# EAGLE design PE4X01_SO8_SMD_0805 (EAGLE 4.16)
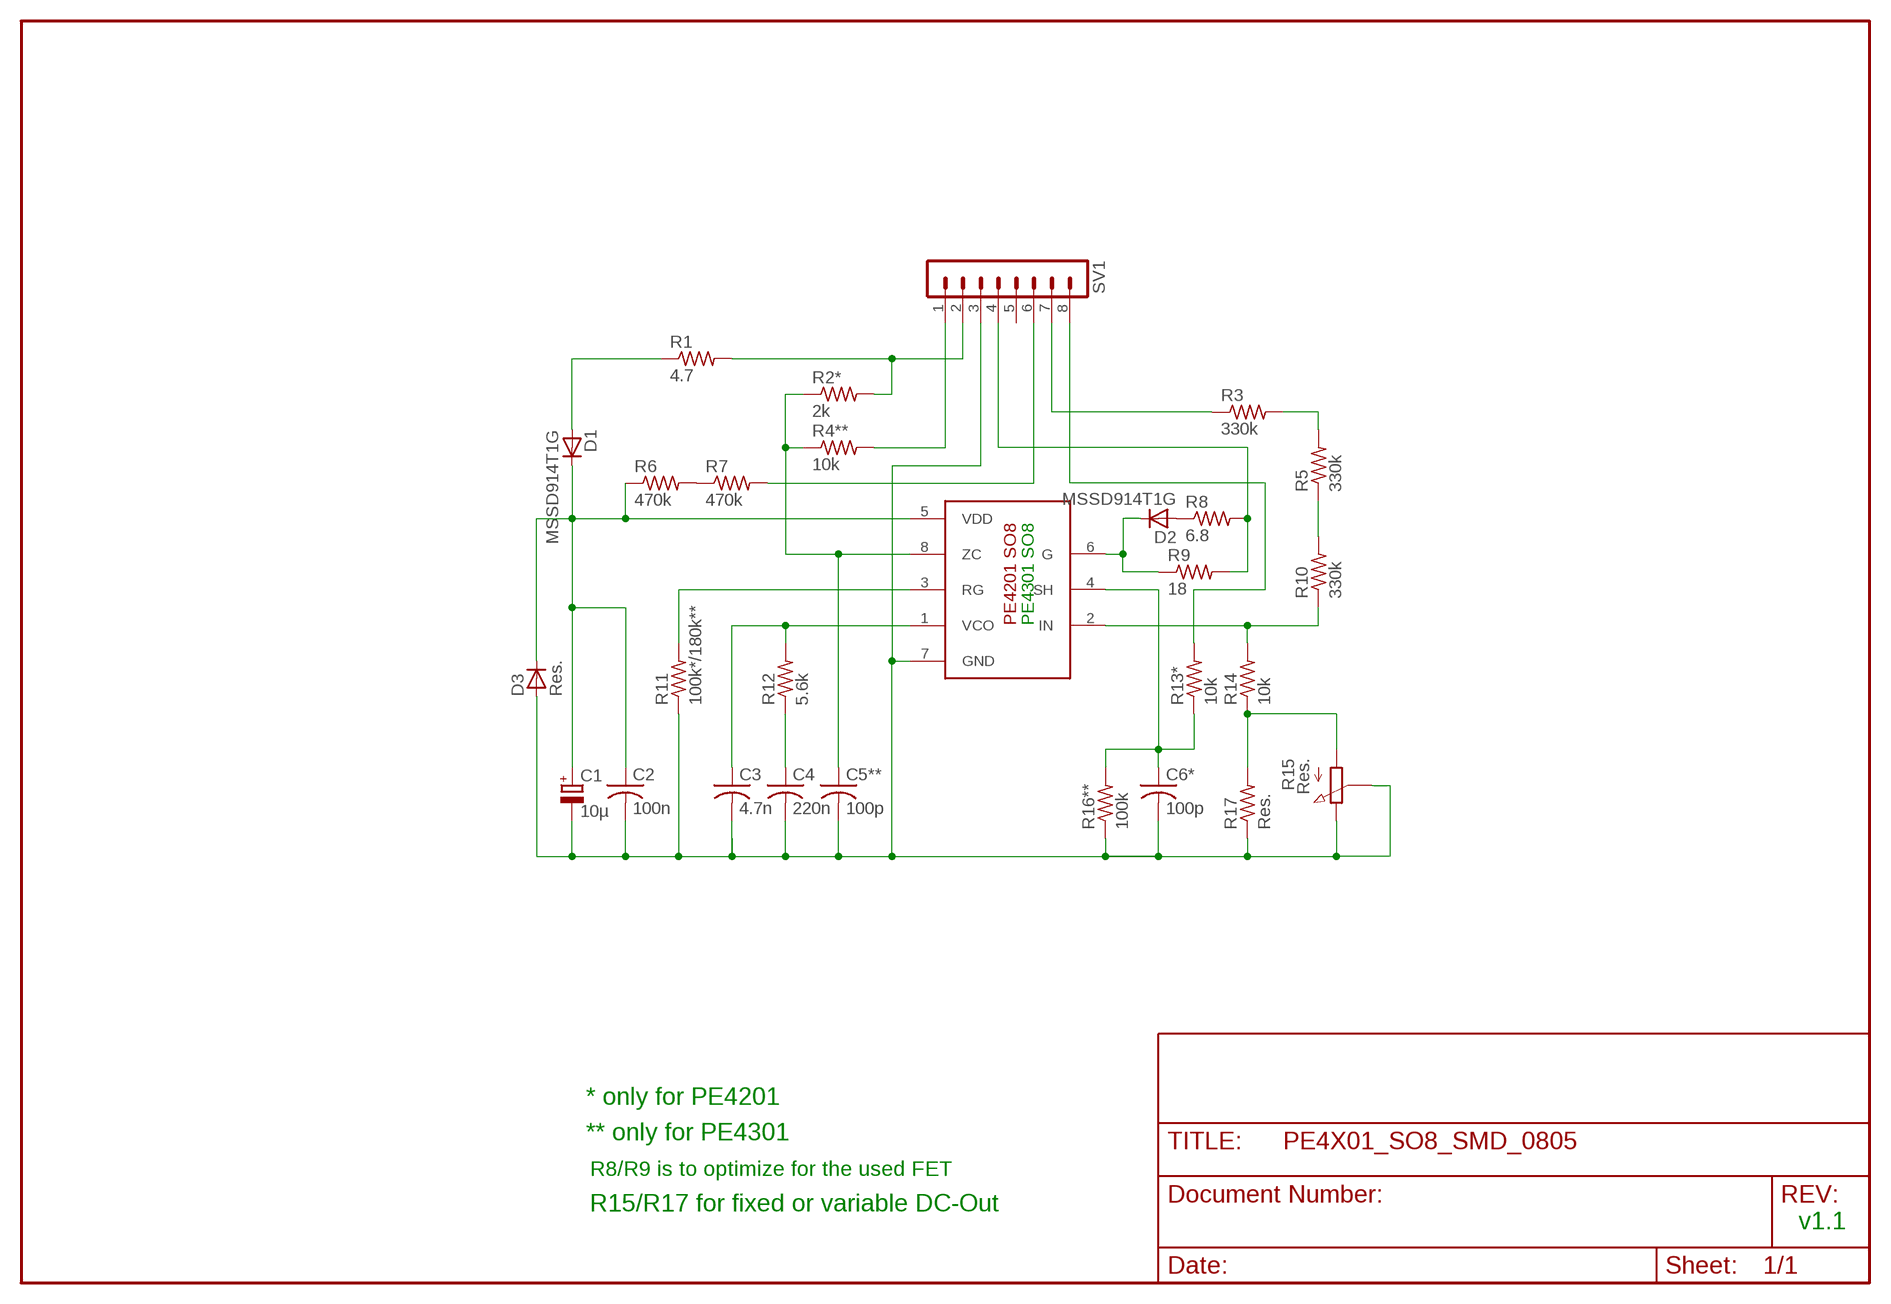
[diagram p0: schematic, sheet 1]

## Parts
C1  10µ  CPOL-EU153CLV-0405  [153CLV-0405]
C2  100n  C-USC1206K  [C1206K]
C3  4.7n  C-USC0805  [C0805]
C4  220n  C-USC0805  [C0805]
C5**  100p  C-USC0805  [C0805]
C6*  100p  C-USC0805  [C0805]
D1  MSSD914T1G  D-SOD123  [SOD123]
D2  MSSD914T1G  D-SOD123  [SOD123]
D3  Res.  D-SOD123  [SOD123]
R1  4.7  R-US_R0805  [R0805]
R2*  2k  R-US_R0805  [R0805]
R3  330k  R-US_R0805  [R0805]
R4**  10k  R-US_R0805  [R0805]
R5  330k  R-US_R0805  [R0805]
R6  470k  R-US_R0805  [R0805]
R7  470k  R-US_R0805  [R0805]
R8  6.8  R-US_R0805  [R0805]
R9  18  R-US_R0805  [R0805]
R10  330k  R-US_R0805  [R0805]
R11  100k*/180k**  R-US_R0805  [R0805]
R12  5.6k  R-US_R0805  [R0805]
R13*  10k  R-US_R0805  [R0805]
R14  10k  R-US_R0805  [R0805]
R15  Res.  PC25  [PC25]
R16**  100k  R-US_R0805  [R0805]
R17  Res.  R-US_R0805  [R0805]
SV1  MA08-1  [MA08-1]
U$1  PE4201/4301_SO08  PE4201_SO08  [PE4201_SO08]

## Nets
++: C6*.1 R13*.1 R16**.2 U$1.4(SH)
A1: C1.+ C2.1 D1.1(C) D3.1(C) R6.1 U$1.5(VDD)
A3: R11.2 U$1.3(RG)
A4: C3.1 R12.2 U$1.1(VCO)
CS: C5**.1 R2*.1 R4**.1 U$1.8(ZC)
GND: C1.- C2.2 C3.2 C4.2 C5**.2 C6*.2 D3.2(A) R11.1 R15.E R15.S R16**.1 R17.1 SV1.3 U$1.7(GND)
N$6: D2.1(C) R9.1 U$1.6(G)
N$9: D2.2(A) R8.1
N$12: R6.2 R7.1
N$13: R1.2 R2*.2 SV1.2
N$14: R10.1 R14.2 U$1.2(IN)
N$16: R5.1 R10.2
N$19: R7.2 SV1.6
N$21: R4**.2 SV1.1
N$22: C4.1 R12.1
N$23: R3.2 R5.2
N$24: R3.1 SV1.7
N$25: R8.2 R9.2 SV1.4
N$26: R13*.2 SV1.8
N$27: D1.2(A) R1.1
N$28: R14.1 R15.A R17.2
Unconnected: SV1.5

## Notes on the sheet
- PE4301 SO8
- * only for PE4201
- ** only for PE4301
- R8/R9 is to optimize for the used FET
- R15/R17 for fixed or variable DC-Out
- v1.1

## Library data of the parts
C1 = rcl:CPOL-EU: POLARIZED CAPACITOR, European symbol
C2-C4 C5** C6* = rcl:C-US: CAPACITOR, American symbol
D1-D3 = semicon-smd-ipc:D-: DIODE
R1 R2* R3 R4** R5-R12 R13* R14 R16** R17 = rcl:R-US_: RESISTOR, American symbol
R15 = pot-vitrohm:PC25: VITROHM POTENTIOMETER
SV1 = con-lstb:MA08-1: PIN HEADER
U$1 = PE4201:PE4201_SO08

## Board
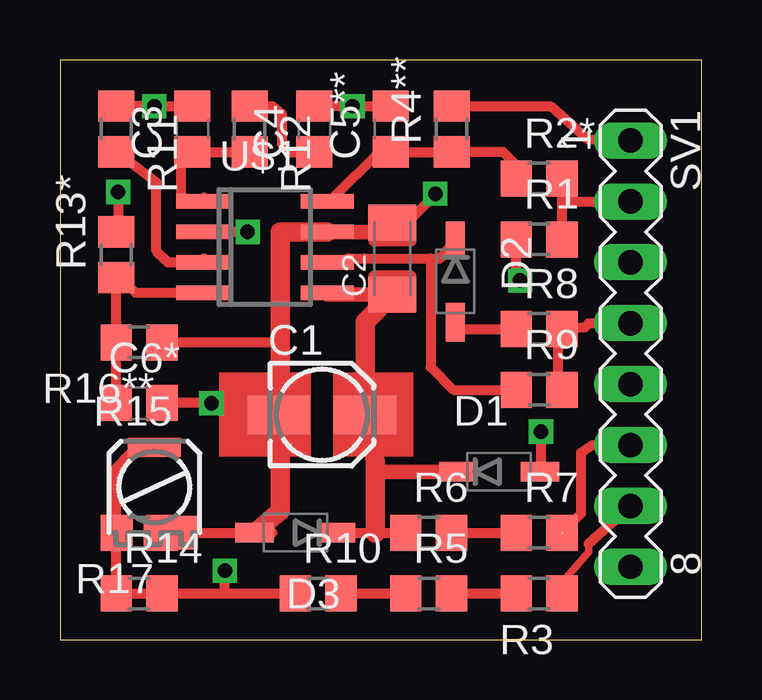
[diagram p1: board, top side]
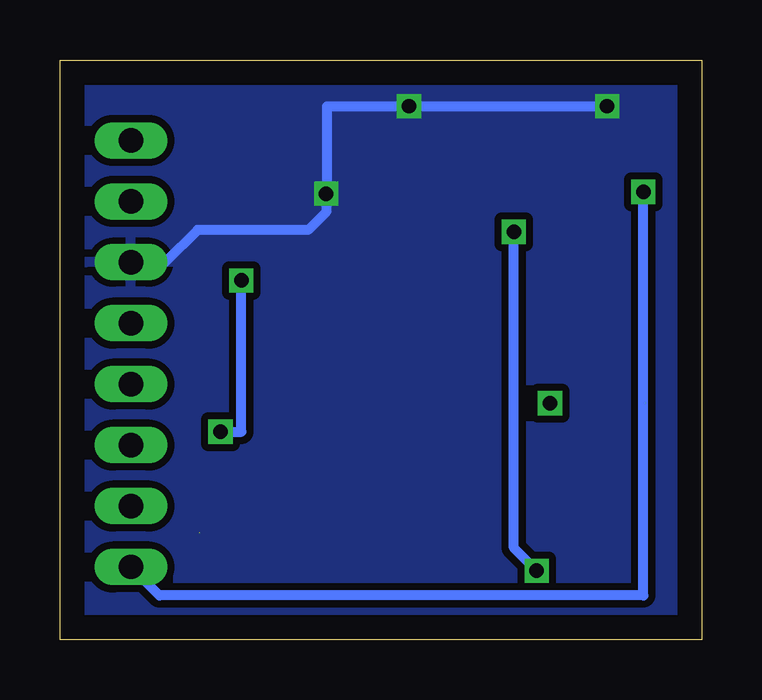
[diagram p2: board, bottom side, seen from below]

Size 26.73 x 24.18 mm. Coordinates in mm from the lower left corner, seen from the top.
Outline: 0,0 26.73,0 26.73,24.18 0,24.18 0,0
Copper layers (1*16): Top 0.035mm / dielectric 1.5mm / Bottom 0.035mm
Design rules "default": minimum track width 10mil, minimum drill 24mil, track to track 8mil, track to pad 8mil, pad to pad 8mil, via to via 8mil, smd to smd 8mil, copper to edge 40mil, drill to drill 8mil, minimum pad ring 10mil, minimum via ring 8mil, stop-mask expansion 4mil, vias tented up to drill 0mil, thermal gap 10mil

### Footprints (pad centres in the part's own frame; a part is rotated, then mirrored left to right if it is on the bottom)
153CLV-0405 = smd 2.6 x 1.6: + 1.8,0; - -1.8,0
C1206K = smd 1.5 x 2: 1 -1.5,0; 2 1.5,0
C0805 = smd 1.3 x 1.5: 1 -0.95,0; 2 0.95,0
SOD123 = smd 1.6 x 0.8: 1 -1.7,0; 2 1.7,0
R0805 = smd 1.3 x 1.5: 1 -0.95,0; 2 0.95,0
PC25 = smd 2.2 x 0.8: 4 0,1.65 | smd 0.9 x 1.4: A -1.35,-1.9; E 1.35,-1.9; S 0,-1.9
MA08-1 = drill 1.016 long: 1 -8.89,0; 2 -6.35,0; 3 -3.81,0; 4 -1.27,0; 5 1.27,0; 6 3.81,0; 7 6.35,0; 8 8.89,0
PE4201_SO08 = smd 0.6 x 2.2: 1 -1.905,-2.6; 2 -0.635,-2.6; 3 0.635,-2.6; 4 1.905,-2.6; 5 1.905,2.6; 6 0.635,2.6; 7 -0.635,2.6; 8 -1.905,2.6

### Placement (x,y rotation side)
C1  10.92,9.39 0 top
C2  13.85,15.9 90 top
C3  5.52,21.29 90 top
C4  10.6,21.29 90 top
C5**  13.77,21.29 90 top
C6*  3.3,9.86 0 top
D1  18.3,7.01 0 top
D2  16.47,14.94 270 top
D3  9.8,4.47 180 top
R1  19.96,16.69 0 top
R2*  19.97,19.23 0 top
R3  19.96,1.93 180 top
R4**  16.31,21.29 90 top
R5  15.36,1.93 0 top
R6  15.36,4.47 0 top
R7  19.96,4.47 0 top
R8  19.96,12.96 0 top
R9  19.97,10.42 0 top
R10  10.76,1.93 0 top
R11  2.34,21.29 270 top
R12  7.9,21.29 270 top
R13*  2.34,16.06 90 top
R14  3.3,1.93 0 top
R15  3.93,6.37 0 top
R16**  3.3,12.4 180 top
R17  3.3,4.47 180 top
SV1  23.77,11.93 270 top
U$1  8.54,16.37 270 top

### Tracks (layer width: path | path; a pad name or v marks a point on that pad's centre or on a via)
++  (1 unrouted)
  Top 0.406: 2.35,15.26 2.34,14.63 2.34,13.2 | C6*.1 2.34,13.2 | 2.34,13.2 R16**.2 | U$1.4 3.93,14.47 3.14,14.47 2.35,15.26 | 2.35,15.26 R13*.1
A1
  Top 0.406: 13.11,8.07 13.14,9.07 13.03,9.07 C1.+ | D3.1 13.14,4.47 R6.1 | 13.85,14.39 C2.1 | 11.08,14.47 | 11.08,14.47 U$1.5 | 11.15,14.4 11.08,14.47
  Top 0.61: 13.14,7.01 D1.1 | C2.1 11.15,14.4
  Top 0.813: 13.14,4.47 13.14,6.53 13.14,7.01 13.11,8.07 | C1.+ 12.72,13.25 13.85,14.39
A3
  Top 0.406: R11.2 4.01,19.07 4.01,16.22 4.49,15.74 U$1.3 5.99,15.9
A4
  Top 0.406: 5.99,18.44 U$1.1 5.04,18.44 5.04,20.34 C3.1 R12.2
CS
  Top 0.406: U$1.8 11.39,18.44 13.3,20.34 13.61,20.34 C5**.1 13.62,20.34 16.47,20.34 R4**.1 18.45,20.35 19.01,19.79 19.01,19.07 R2*.1
GND  (via drill 0.6)
  Top 0.406: 9.17,12.41 R16**.1 | 8.85,4.47 D3.2 R15.E | R15.E R17.1 | C1.- 9.17,9.86 C6*.2 | C5**.2 12.74,22.25 v12.19,22.25 11.63,22.25 C4.2 | R11.1 3.29,22.25 v3.93,22.25 4.41,22.25 C3.2 | 13.46,17.41 C2.2 | v15.64,18.6 15.68,18.6 14.49,17.41 13.46,17.41 | 13.46,17.01 13.46,17.41 | R15.E | R15.S R15.E
  Top 0.61: U$1.7 13.46,17.01
  Top 0.813: U$1.7 9.17,17.01 9.17,12.41 9.17,9.86 9.17,5.37 D3.2
  Bottom 0.406: 16.39,17.09 21,17.09 22.35,15.74 SV1.3 | v3.93,22.25 v12.19,22.25 15.6,22.25 15.6,18.6 v15.64,18.6 15.64,17.84 16.39,17.09 | 16.39,17.09
  pour Bottom (isolate 0.305): -0.04,24.15 27.11,24.15 27.11,0.02 -0.04,0.02 -0.04,24.23 0.04,24.15
N$1  (via drill 0.6)
  other vias: 6.31,9.86
N$2
  Top 0.406: 14.65,15.18 13.06,15.18
N$3
  Top 0.406: 2.98,7.8 2.34,7.17 2.34,4.47
N$4
  Top 0.406: 14.65,16.61 13.06,16.61
N$6
  Top 0.406: 15.44,15.9 12.66,15.9 12.03,15.9 U$1.6 | 15.44,15.9 15.44,11.37 16.39,10.42 R9.1 | D2.1 15.84,15.9 15.44,15.9
N$9
  Top 0.406: D2.2 16.27,12.96 R8.1
N$12
  Top 0.406: R6.2 R7.1
N$13
  Top 0.406: R1.2 20.92,16.21 20.92,19.07 R2*.2 20.92,18.28 SV1.2
N$14  (via drill 0.6)
  Top 0.406: 6.87,1.93 6.95,1.93 | 10.12,1.93 R10.1 6.87,1.93 | v7.82,17.01 U$1.2 | v7.82,17.01 | R14.2 6.87,1.93 | 6.87,1.93 v6.87,2.88
  Bottom 0.406: 6.87,2.8 v6.87,2.88 7.82,3.83 v7.82,17.01
N$16
  Top 0.406: R10.2 R5.1
N$19  (1 unrouted)
  Top 0.406: SV1.6 22.19,8.12 21.71,7.8 21.71,5.26 R7.2
N$21
  Top 0.406: SV1.1 21.97,20.87 20.44,22.25 R4**.2
N$22
  Top 0.406: R12.1 8.86,22.25 9.25,21.93 9.25,20.66 9.49,20.34 10.76,20.34 C4.1
N$23
  Top 0.406: R5.2 R3.2
N$24
  Top 0.305: 20.92,2.4 22.03,3.67 22.03,3.99
  Top 0.406: R3.1 20.92,2.4 | 22.03,3.99 SV1.7
N$25
  Top 0.406: SV1.4 22.03,13.2 21.87,13.04 R8.2 20.76,13.36 20.76,10.18 | 20.66,10.13 20.76,10.18 | R9.2 20.92,10.34 20.76,10.18
N$26  (via drill 0.6)
  Top 0.406: R13*.2 2.42,17.4 v2.42,18.68
  Bottom 0.406: v2.42,18.68 2.42,1.85 22.58,1.85 SV1.8
N$27  (via drill 0.6)
  Top 0.406: D1.2 20.04,7.05 v20.04,8.67 | R1.1 19.01,15.14 v19.17,14.98
  Bottom 0.406: v19.17,14.98 19.17,8.67 v20.04,8.67
N$28
  Top 0.406: R14.1 5.2,1.93 R14.1 R17.2 R15.A
(copper drawn outside any net)
  shapes: Top area x2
